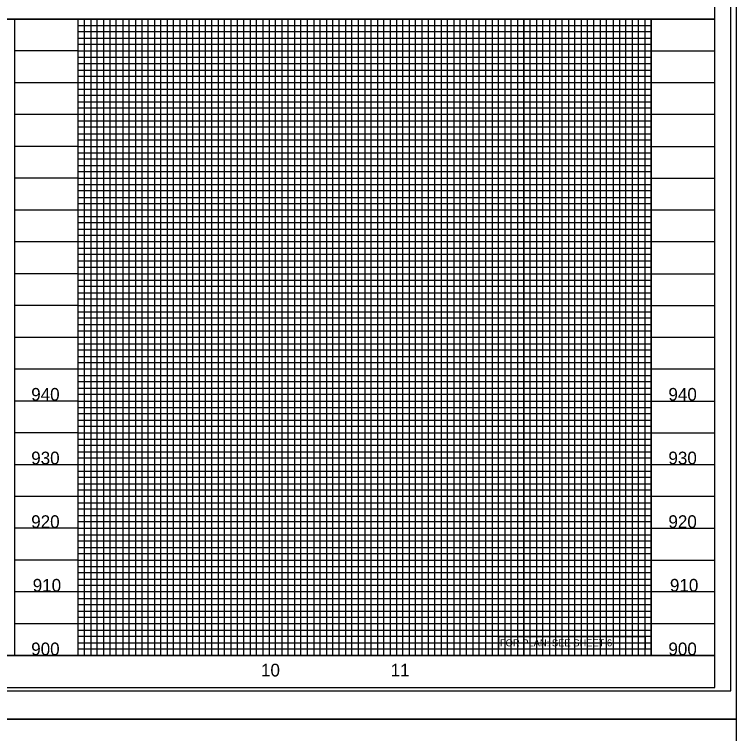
# Model space of a CAD drawing. Extents: x 1967929 to 1975641, y 546296 to 568534.
# Drawn here: x 1970981 to 1971548, y 565223 to 565788 of the extents above; entities that cross this region are included whole.
import ezdxf

# ---------------------------------------------------------------- set-up
doc = ezdxf.new("R2010")
doc.units = 0
for name, color, linetype in [('Exist Vertical Profile Horizontal Axis Label Major', 7, 'Continuous'), ('Exist Vertical Profile Vertical Axis Label', 7, 'Continuous'), ('Prop Grid Mask', 7, 'Continuous'), ('Scratch_Level_3', 7, 'Continuous'), ('Sheet Cutting Line CELL', 7, 'Continuous'), ('Sheet Plot Border Inside CELL', 7, 'Continuous'), ('Sheet Plot Border Outside CELL', 7, 'Continuous'), ('Sheet Profile CELL', 7, 'Continuous'), ('Sheet Profile Grid Major CELL', 7, 'Continuous'), ('Sheet Profile Grid Middle CELL', 7, 'Continuous'), ('Sheet Profile Grid Minor CELL', 7, 'Continuous')]:
    doc.layers.add(name, color=color, linetype=linetype)

msp = doc.modelspace()

# ---------------------------------------------------------------- linework, layer by layer
at = {"layer": 'Prop Grid Mask'}
msp.add_lwpolyline([(1971361.72, 565298.9), (1971476.6, 565298.9), (1971476.6, 565288.87), (1971361.72, 565288.87)], close=True, dxfattribs=at)
at = {"layer": 'Scratch_Level_3'}
for points in [[(1970081.45, 565783.86), (1970081.45, 565283.86), (1971481.45, 565283.86), (1971481.45, 565783.86)], [(1970081.45, 565783.86), (1970081.45, 565283.86), (1971381.45, 565283.86), (1971381.45, 565783.86)], [(1970081.45, 565783.86), (1970081.45, 565283.86), (1971481.45, 565283.86), (1971481.45, 565783.86)]]:
    msp.add_lwpolyline(points, close=True, dxfattribs=at)
at = {"layer": 'Sheet Cutting Line CELL'}
msp.add_line((1969864.45, 565233.86), (1971548.45, 565233.86), dxfattribs=at)
at = {"layer": 'Sheet Plot Border Inside CELL'}
msp.add_lwpolyline([(1969877.45, 565256.31), (1971543.95, 565256.31), (1971543.95, 566311.41), (1969877.45, 566311.41)], close=True, dxfattribs=at)
at = {"layer": 'Sheet Plot Border Outside CELL'}
for points in [[(1969864.45, 565233.86), (1971548.45, 565233.86), (1971548.45, 566333.86), (1969864.45, 566333.86)], [(1969864.45, 564133.86), (1971548.45, 564133.86), (1971548.45, 565233.86), (1969864.45, 565233.86)]]:
    msp.add_lwpolyline(points, close=True, dxfattribs=at)
at = {"layer": 'Sheet Profile CELL'}
for p, q in [((1971531.45, 565783.86), (1970031.45, 565783.86)), ((1971531.45, 565283.86), (1970031.45, 565283.86))]:
    msp.add_line(p, q, dxfattribs=at)
msp.add_lwpolyline([(1971531.45, 566308.86), (1970031.45, 566308.86), (1970031.45, 565258.86), (1971531.45, 565258.86)], close=True, dxfattribs=at)
at = {"layer": 'Sheet Profile Grid Major CELL'}
for points in [[(1970531.45, 565733.86), (1970031.45, 565733.86), (1970031.45, 565783.86), (1971531.45, 565783.86)], [(1970981.45, 565288.86), (1970981.45, 565283.86), (1971031.45, 565283.86), (1971031.45, 565783.86)], [(1970981.45, 565783.86), (1970981.45, 565283.86), (1971031.45, 565283.86), (1971031.45, 565783.86)], [(1971081.45, 565783.86), (1971081.45, 565283.86), (1971131.45, 565283.86), (1971131.45, 565783.86)], [(1971181.45, 565783.86), (1971181.45, 565283.86), (1971231.45, 565283.86), (1971231.45, 565783.86)], [(1971281.45, 565783.86), (1971281.45, 565283.86), (1971331.45, 565283.86), (1971331.45, 565783.86)], [(1971381.45, 565783.86), (1971381.45, 565283.86), (1971431.45, 565283.86), (1971431.45, 565783.86)], [(1971481.45, 565783.86), (1971481.45, 565283.86), (1971531.45, 565283.86)], [(1971031.45, 565733.86), (1970981.45, 565733.86)], [(1971531.45, 565733.86), (1971031.45, 565733.86)], [(1971031.45, 565683.86), (1970981.45, 565683.86)], [(1971031.45, 565683.86), (1971531.45, 565683.86)], [(1971031.45, 565633.86), (1970981.45, 565633.86)], [(1971531.45, 565633.86), (1971031.45, 565633.86)], [(1971031.45, 565583.86), (1970981.45, 565583.86)], [(1971031.45, 565583.86), (1971531.45, 565583.86)], [(1971031.45, 565533.86), (1970981.45, 565533.86)], [(1971531.45, 565533.86), (1971031.45, 565533.86)], [(1971031.45, 565483.86), (1970981.45, 565483.86)], [(1971031.45, 565483.86), (1971531.45, 565483.86)], [(1971031.45, 565433.86), (1970981.45, 565433.86)], [(1971531.45, 565433.86), (1971031.45, 565433.86)], [(1971031.45, 565383.86), (1970981.45, 565383.86)], [(1971031.45, 565383.86), (1971531.45, 565383.86)], [(1971031.45, 565333.86), (1970981.45, 565333.86)], [(1971531.45, 565333.86), (1971031.45, 565333.86)]]:
    msp.add_lwpolyline(points, dxfattribs=at)
at = {"layer": 'Sheet Profile Grid Middle CELL'}
msp.add_line((1970956.45, 565283.86), (1971006.45, 565283.86), dxfattribs=at)
for points in [[(1971056.45, 565783.86), (1971056.45, 565283.86), (1971106.45, 565283.86), (1971106.45, 565783.86)], [(1971156.45, 565783.86), (1971156.45, 565283.86), (1971206.45, 565283.86), (1971206.45, 565783.86)], [(1971256.45, 565783.86), (1971256.45, 565283.86), (1971306.45, 565283.86), (1971306.45, 565783.86)], [(1971356.45, 565783.86), (1971356.45, 565283.86), (1971406.45, 565283.86), (1971406.45, 565783.86)], [(1971456.45, 565783.86), (1971456.45, 565283.86)], [(1971031.45, 565758.86), (1970981.45, 565758.86)], [(1971031.45, 565758.86), (1971531.45, 565758.86)], [(1971031.45, 565708.86), (1970981.45, 565708.86)], [(1971531.45, 565708.86), (1971031.45, 565708.86)], [(1971031.45, 565658.86), (1970981.45, 565658.86)], [(1971031.45, 565658.86), (1971531.45, 565658.86)], [(1971031.45, 565608.86), (1970981.45, 565608.86)], [(1971531.45, 565608.86), (1971031.45, 565608.86)], [(1971031.45, 565558.86), (1970981.45, 565558.86)], [(1971031.45, 565558.86), (1971531.45, 565558.86)], [(1971031.45, 565508.86), (1970981.45, 565508.86)], [(1971531.45, 565508.86), (1971031.45, 565508.86)], [(1971031.45, 565458.86), (1970981.45, 565458.86)], [(1971031.45, 565458.86), (1971531.45, 565458.86)], [(1971031.45, 565408.86), (1970981.45, 565408.86)], [(1971531.45, 565408.86), (1971031.45, 565408.86)], [(1971031.45, 565358.86), (1970981.45, 565358.86)], [(1971031.45, 565358.86), (1971531.45, 565358.86)], [(1971031.45, 565308.86), (1970981.45, 565308.86)], [(1971531.45, 565308.86), (1971031.45, 565308.86)]]:
    msp.add_lwpolyline(points, dxfattribs=at)
at = {"layer": 'Sheet Profile Grid Minor CELL'}
for p, q in [((1971036.45, 565283.86), (1971036.45, 565783.86)), ((1970976.45, 565283.86), (1970986.45, 565283.86)), ((1971026.45, 565283.86), (1971036.45, 565283.86))]:
    msp.add_line(p, q, dxfattribs=at)
for points in [[(1971041.45, 565783.86), (1971041.45, 565283.86), (1971046.45, 565283.86), (1971046.45, 565783.86)], [(1971051.45, 565783.86), (1971051.45, 565283.86), (1971061.45, 565283.86), (1971061.45, 565783.86)], [(1971066.45, 565783.86), (1971066.45, 565283.86), (1971071.45, 565283.86), (1971071.45, 565783.86)], [(1971076.45, 565783.86), (1971076.45, 565283.86), (1971086.45, 565283.86), (1971086.45, 565783.86)], [(1971091.45, 565783.86), (1971091.45, 565283.86), (1971096.45, 565283.86), (1971096.45, 565783.86)], [(1971101.45, 565783.86), (1971101.45, 565283.86)], [(1971101.45, 565283.86), (1971111.45, 565283.86), (1971111.45, 565783.86)], [(1971116.45, 565783.86), (1971116.45, 565283.86), (1971121.45, 565283.86), (1971121.45, 565783.86)], [(1971126.45, 565783.86), (1971126.45, 565283.86), (1971136.45, 565283.86), (1971136.45, 565783.86)], [(1971141.45, 565783.86), (1971141.45, 565283.86), (1971146.45, 565283.86), (1971146.45, 565783.86)], [(1971151.45, 565783.86), (1971151.45, 565283.86), (1971161.45, 565283.86), (1971161.45, 565783.86)], [(1971166.45, 565783.86), (1971166.45, 565283.86), (1971171.45, 565283.86), (1971171.45, 565783.86)], [(1971176.45, 565783.86), (1971176.45, 565283.86), (1971186.45, 565283.86), (1971186.45, 565783.86)], [(1971191.45, 565783.86), (1971191.45, 565283.86), (1971196.45, 565283.86), (1971196.45, 565783.86)], [(1971201.45, 565783.86), (1971201.45, 565283.86), (1971211.45, 565283.86), (1971211.45, 565783.86)], [(1971216.45, 565783.86), (1971216.45, 565283.86), (1971221.45, 565283.86), (1971221.45, 565783.86)], [(1971226.45, 565783.86), (1971226.45, 565283.86), (1971236.45, 565283.86), (1971236.45, 565783.86)], [(1971241.45, 565783.86), (1971241.45, 565283.86), (1971246.45, 565283.86), (1971246.45, 565783.86)], [(1971251.45, 565783.86), (1971251.45, 565283.86), (1971261.45, 565283.86), (1971261.45, 565783.86)], [(1971266.45, 565783.86), (1971266.45, 565283.86), (1971271.45, 565283.86), (1971271.45, 565783.86)], [(1971276.45, 565783.86), (1971276.45, 565283.86), (1971286.45, 565283.86), (1971286.45, 565783.86)], [(1971291.45, 565783.86), (1971291.45, 565283.86), (1971296.45, 565283.86), (1971296.45, 565783.86)], [(1971301.45, 565783.86), (1971301.45, 565283.86), (1971311.45, 565283.86), (1971311.45, 565783.86)], [(1971316.45, 565783.86), (1971316.45, 565283.86), (1971321.45, 565283.86), (1971321.45, 565783.86)], [(1971326.45, 565783.86), (1971326.45, 565283.86), (1971336.45, 565283.86), (1971336.45, 565783.86)], [(1971341.45, 565783.86), (1971341.45, 565283.86), (1971346.45, 565283.86), (1971346.45, 565783.86)], [(1971351.45, 565783.86), (1971351.45, 565283.86), (1971361.45, 565283.86), (1971361.45, 565783.86)], [(1971366.45, 565783.86), (1971366.45, 565283.86), (1971371.45, 565283.86), (1971371.45, 565783.86)], [(1971376.45, 565783.86), (1971376.45, 565283.86), (1971386.45, 565283.86), (1971386.45, 565783.86)], [(1971391.45, 565783.86), (1971391.45, 565283.86), (1971396.45, 565283.86), (1971396.45, 565783.86)], [(1971401.45, 565783.86), (1971401.45, 565283.86), (1971411.45, 565283.86), (1971411.45, 565783.86)], [(1971416.45, 565783.86), (1971416.45, 565283.86)], [(1971416.45, 565283.86), (1971421.45, 565283.86), (1971421.45, 565783.86)], [(1971426.45, 565783.86), (1971426.45, 565283.86), (1971436.45, 565283.86), (1971436.45, 565783.86)], [(1971441.45, 565783.86), (1971441.45, 565283.86), (1971446.45, 565283.86), (1971446.45, 565783.86)], [(1971451.45, 565783.86), (1971451.45, 565283.86), (1971461.45, 565283.86), (1971461.45, 565783.86)], [(1971466.45, 565783.86), (1971466.45, 565283.86), (1971471.45, 565283.86), (1971471.45, 565783.86)], [(1971476.45, 565783.86), (1971476.45, 565283.86), (1971486.45, 565283.86)], [(1971031.45, 565778.86), (1971481.45, 565778.86)], [(1971481.45, 565773.86), (1971031.45, 565773.86)], [(1971031.45, 565768.86), (1971481.45, 565768.86)], [(1971481.45, 565763.86), (1971031.45, 565763.86)], [(1971031.45, 565753.86), (1971481.45, 565753.86)], [(1971481.45, 565748.86), (1971031.45, 565748.86)], [(1971031.45, 565743.86), (1971481.45, 565743.86)], [(1971481.45, 565738.86), (1971031.45, 565738.86)], [(1971031.45, 565728.86), (1971481.45, 565728.86)], [(1971481.45, 565723.86), (1971031.45, 565723.86)], [(1971031.45, 565718.86), (1971481.45, 565718.86)], [(1971481.45, 565713.86), (1971031.45, 565713.86)], [(1971031.45, 565703.86), (1971481.45, 565703.86)], [(1971481.45, 565698.86), (1971031.45, 565698.86)], [(1971031.45, 565693.86), (1971481.45, 565693.86)], [(1971481.45, 565688.86), (1971031.45, 565688.86)], [(1971031.45, 565678.86), (1971481.45, 565678.86)], [(1971481.45, 565673.86), (1971031.45, 565673.86)], [(1971031.45, 565668.86), (1971481.45, 565668.86)], [(1971481.45, 565663.86), (1971031.45, 565663.86)], [(1971031.45, 565653.86), (1971481.45, 565653.86)], [(1971481.45, 565648.86), (1971031.45, 565648.86)], [(1971031.45, 565643.86), (1971481.45, 565643.86)], [(1971481.45, 565638.86), (1971031.45, 565638.86)], [(1971031.45, 565628.86), (1971481.45, 565628.86)], [(1971481.45, 565623.86), (1971031.45, 565623.86)], [(1971031.45, 565618.86), (1971481.45, 565618.86)], [(1971481.45, 565613.86), (1971031.45, 565613.86)], [(1971031.45, 565603.86), (1971481.45, 565603.86)], [(1971481.45, 565598.86), (1971031.45, 565598.86)], [(1971031.45, 565593.86), (1971481.45, 565593.86)], [(1971481.45, 565588.86), (1971031.45, 565588.86)], [(1971031.45, 565578.86), (1971481.45, 565578.86)], [(1971481.45, 565573.86), (1971031.45, 565573.86)], [(1971031.45, 565568.86), (1971481.45, 565568.86)], [(1971481.45, 565563.86), (1971031.45, 565563.86)], [(1971031.45, 565553.86), (1971481.45, 565553.86)], [(1971481.45, 565548.86), (1971031.45, 565548.86)], [(1971031.45, 565543.86), (1971481.45, 565543.86)], [(1971481.45, 565538.86), (1971031.45, 565538.86)], [(1971031.45, 565528.86), (1971481.45, 565528.86)], [(1971481.45, 565523.86), (1971031.45, 565523.86)], [(1971031.45, 565518.86), (1971481.45, 565518.86)], [(1971481.45, 565513.86), (1971031.45, 565513.86)], [(1971031.45, 565503.86), (1971481.45, 565503.86)], [(1971481.45, 565498.86), (1971031.45, 565498.86)], [(1971031.45, 565493.86), (1971481.45, 565493.86)], [(1971481.45, 565488.86), (1971031.45, 565488.86)], [(1971031.45, 565478.86), (1971481.45, 565478.86)], [(1971481.45, 565473.86), (1971031.45, 565473.86)], [(1971031.45, 565468.86), (1971481.45, 565468.86)], [(1971481.45, 565463.86), (1971031.45, 565463.86)], [(1971031.45, 565453.86), (1971481.45, 565453.86)], [(1971481.45, 565448.86), (1971031.45, 565448.86)], [(1971031.45, 565443.86), (1971481.45, 565443.86)], [(1971481.45, 565438.86), (1971031.45, 565438.86)], [(1971031.45, 565428.86), (1971481.45, 565428.86)], [(1971481.45, 565423.86), (1971031.45, 565423.86)], [(1971031.45, 565418.86), (1971481.45, 565418.86)], [(1971481.45, 565413.86), (1971031.45, 565413.86)], [(1971031.45, 565403.86), (1971481.45, 565403.86)], [(1971481.45, 565398.86), (1971031.45, 565398.86)], [(1971031.45, 565393.86), (1971481.45, 565393.86)], [(1971481.45, 565388.86), (1971031.45, 565388.86)], [(1971031.45, 565378.86), (1971481.45, 565378.86)], [(1971481.45, 565373.86), (1971031.45, 565373.86)], [(1971031.45, 565368.86), (1971481.45, 565368.86)], [(1971481.45, 565363.86), (1971031.45, 565363.86)], [(1971031.45, 565353.86), (1971481.45, 565353.86)], [(1971481.45, 565348.86), (1971031.45, 565348.86)], [(1971031.45, 565343.86), (1971481.45, 565343.86)], [(1971481.45, 565338.86), (1971031.45, 565338.86)], [(1971031.45, 565328.86), (1971481.45, 565328.86)], [(1971481.45, 565323.86), (1971031.45, 565323.86)], [(1971031.45, 565318.86), (1971481.45, 565318.86)], [(1971481.45, 565313.86), (1971031.45, 565313.86)], [(1971031.45, 565303.86), (1971481.45, 565303.86)], [(1971481.45, 565298.86), (1971031.45, 565298.86)], [(1971031.45, 565293.86), (1971481.45, 565293.86)], [(1971481.45, 565288.86), (1971031.45, 565288.86)]]:
    msp.add_lwpolyline(points, dxfattribs=at)

# ---------------------------------------------------------------- texts
at = {"layer": 'Exist Vertical Profile Horizontal Axis Label Major'}
for s, p in [('10', (1971175.03, 565267.47)), ('11', (1971276.87, 565267.47))]:
    msp.add_text(s, height=10, dxfattribs=at).set_placement(p)
at = {"layer": 'Exist Vertical Profile Vertical Axis Label'}
for s, p in [('940', (1970994.61, 565484.11)), ('940', (1971494.94, 565484.11)), ('930', (1970994.61, 565434.11)), ('930', (1971494.94, 565434.11)), ('920', (1970994.61, 565384.11)), ('920', (1971494.94, 565384.11)), ('910', (1970995.8, 565334.11)), ('910', (1971496.14, 565334.11)), ('900', (1970994.61, 565284.11)), ('900', (1971494.94, 565284.11))]:
    msp.add_text(s, height=10, dxfattribs=at).set_placement(p)
at = {"layer": 'Prop Grid Mask'}
msp.add_text('FOR PLAN: SEE SHEET 6', height=5.4932, dxfattribs=at).set_placement((1971362.61, 565291.16))

doc.saveas('drawing.dxf')
